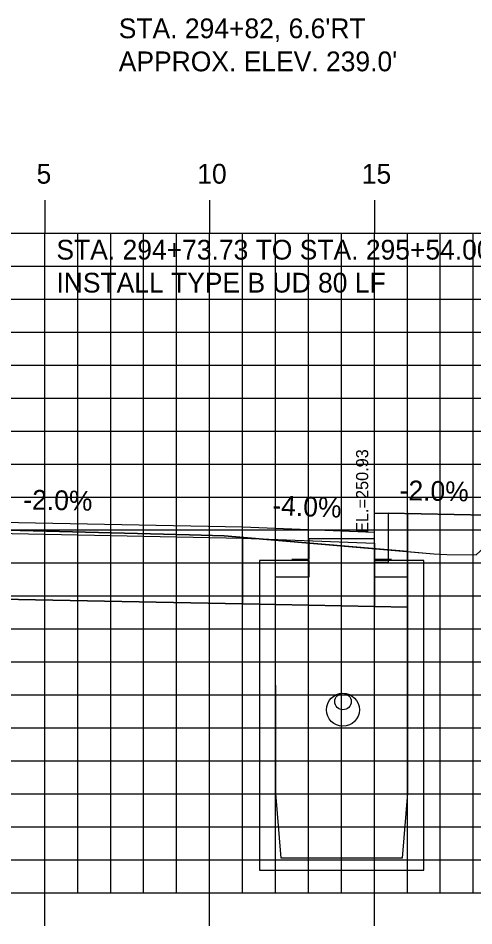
# Model space of a CAD drawing. Extents: x 859352 to 859522, y 366268 to 366378.
# Drawn here: x 859439.32 to 859453.15, y 366306.23 to 366333.75 of the extents above; entities that cross this region are included whole.
import ezdxf

# ---------------------------------------------------------------- set-up
doc = ezdxf.new("R2010")
doc.units = 0
for name, color, linetype in [('ANNOTATION', 7, 'Continuous'), ('D_Curb_Type_1_Rt', 7, 'Continuous'), ('D_Drainage_CB_TypeA1-B1', 7, 'Continuous'), ('D_Drainage_Text', 7, 'Continuous'), ('D_Roadway_Edge_Shoulder', 7, 'Continuous'), ('D_Roadway_FinishedGrade', 7, 'Continuous'), ('D_Roadway_SubGrade', 7, 'Continuous'), ('D_Text_Standard', 7, 'Continuous'), ('H_V ANNOTATION', 7, 'Continuous'), ('JUNK COM EXC', 7, 'Continuous'), ('JUNK FILL', 7, 'Continuous'), ('MAJOR', 7, 'Continuous'), ('MINOR', 7, 'Continuous'), ('PDRAIN', 7, 'Continuous'), ('ROCKS', 7, 'Continuous'), ('S_Roadway_Centerline', 7, 'Continuous')]:
    doc.layers.add(name, color=color, linetype=linetype)

msp = doc.modelspace()

# ---------------------------------------------------------------- linework, layer by layer
at = {"layer": 'D_Curb_Type_1_Rt'}
msp.add_lwpolyline([(859450.546, 366318.75), (859450.546, 366317.25), (859450.129, 366317.25), (859450.129, 366318.75)], close=True, dxfattribs=at)
at = {"layer": 'D_Drainage_CB_TypeA1-B1'}
for p, q in [((859448.153, 366317.311), (859446.644, 366317.311)), ((859446.644, 366317.311), (859446.644, 366315.31)), ((859448.153, 366316.811), (859448.153, 366317.311)), ((859451.63, 366317.311), (859450.121, 366317.311)), ((859450.121, 366317.311), (859450.121, 366316.811)), ((859451.63, 366315.31), (859451.63, 366317.311)), ((859447.136, 366310.255), (859447.129, 366316.811)), ((859447.129, 366316.811), (859448.153, 366316.811)), ((859450.121, 366316.811), (859451.138, 366316.811)), ((859451.138, 366316.811), (859451.138, 366310.255)), ((859446.644, 366315.31), (859446.644, 366307.926)), ((859451.63, 366307.926), (859451.63, 366315.31)), ((859447.3, 366308.286), (859447.136, 366310.255)), ((859451.138, 366310.255), (859450.974, 366308.286)), ((859450.974, 366308.286), (859447.3, 366308.286)), ((859446.644, 366307.926), (859451.63, 366307.926))]:
    msp.add_line(p, q, dxfattribs=at)
msp.add_lwpolyline([(859447.628, 366317.353), (859448.153, 366317.353), (859448.153, 366317.976), (859450.121, 366317.976), (859450.121, 366317.353), (859450.646, 366317.353)], dxfattribs=at)
at = {"layer": 'D_Roadway_Edge_Shoulder'}
msp.add_lwpolyline([(859420.132, 366318.167), (859424.13, 366318.327), (859435.13, 366318.547), (859446.13, 366318.327), (859450.121, 366318.167)], dxfattribs=at)
at = {"layer": 'D_Roadway_FinishedGrade'}
msp.add_lwpolyline([(859450.546, 366318.749), (859453.546, 366318.689)], dxfattribs=at)
at = {"layer": 'D_Roadway_SubGrade'}
msp.add_lwpolyline([(859451.129, 366318.761), (859451.129, 366315.893), (859450.13, 366315.913)], dxfattribs=at)
for points in [[(859424.13, 366315.993), (859424.13, 366317.993), (859435.13, 366318.213), (859446.13, 366317.993), (859446.13, 366315.993), (859435.13, 366316.213)], [(859446.13, 366317.993), (859450.13, 366317.833), (859450.13, 366315.913), (859446.13, 366315.993)]]:
    msp.add_lwpolyline(points, close=True, dxfattribs=at)
at = {"layer": 'JUNK COM EXC'}
msp.add_lwpolyline([(859415.127, 366318.509), (859415.125, 366317.675), (859419.13, 366317.595), (859419.13, 366315.893), (859424.13, 366315.993), (859435.13, 366316.213), (859446.13, 366315.993), (859451.129, 366315.893), (859451.129, 366317.579), (859445.568, 366318.061), (859444.518, 366318.087), (859435.819, 366318.308), (859426.771, 366318.136), (859425.006, 366318.102), (859424.052, 366318.059), (859421.622, 366317.921), (859421.018, 366317.889), (859420.288, 366317.857), (859419.866, 366318.325), (859419.801, 366318.381), (859418.966, 366318.416), (859415.419, 366318.501), (859415.127, 366318.509)], dxfattribs=at)
at = {"layer": 'JUNK FILL'}
msp.add_lwpolyline([(859451.129, 366317.579), (859451.933, 366317.51), (859452.326, 366317.489), (859453.214, 366317.483), (859453.855, 366318.068), (859458.043, 366317.94), (859455.795, 366318.315), (859453.546, 366318.689), (859450.546, 366318.749), (859450.546, 366317.63)], close=True, dxfattribs=at)
at = {"layer": 'MAJOR'}
for p, q in [((859440.129, 366328.238), (859440.129, 366327.236)), ((859445.129, 366328.238), (859445.129, 366327.236)), ((859450.129, 366328.238), (859450.129, 366327.236)), ((859365.129, 366327.236), (859505.129, 366327.236)), ((859365.129, 366327.236), (859505.129, 366327.236)), ((859440.129, 366307.236), (859440.129, 366327.236)), ((859445.129, 366307.236), (859445.129, 366327.236)), ((859450.129, 366307.236), (859450.129, 366327.236)), ((859365.129, 366322.236), (859505.129, 366322.236)), ((859365.129, 366317.236), (859505.129, 366317.236)), ((859365.129, 366312.236), (859505.129, 366312.236)), ((859365.129, 366307.236), (859505.129, 366307.236)), ((859365.129, 366307.236), (859505.129, 366307.236)), ((859440.129, 366306.234), (859440.129, 366307.236)), ((859445.129, 366306.234), (859445.129, 366307.236)), ((859450.129, 366306.234), (859450.129, 366307.236))]:
    msp.add_line(p, q, dxfattribs=at)
at = {"layer": 'MINOR'}
for p, q in [((859441.129, 366307.236), (859441.129, 366327.236)), ((859442.129, 366307.236), (859442.129, 366327.236)), ((859443.129, 366307.236), (859443.129, 366327.236)), ((859444.129, 366307.236), (859444.129, 366327.236)), ((859446.129, 366307.236), (859446.129, 366327.236)), ((859447.129, 366307.236), (859447.129, 366327.236)), ((859448.129, 366307.236), (859448.129, 366327.236)), ((859449.129, 366307.236), (859449.129, 366327.236)), ((859451.129, 366307.236), (859451.129, 366327.236)), ((859452.129, 366307.236), (859452.129, 366327.236)), ((859453.129, 366307.236), (859453.129, 366327.236)), ((859365.129, 366326.236), (859505.129, 366326.236)), ((859365.129, 366325.236), (859505.129, 366325.236)), ((859365.129, 366324.236), (859505.129, 366324.236)), ((859365.129, 366323.236), (859505.129, 366323.236)), ((859365.129, 366321.236), (859505.129, 366321.236)), ((859365.129, 366320.236), (859505.129, 366320.236)), ((859365.129, 366319.236), (859505.129, 366319.236)), ((859365.129, 366318.236), (859505.129, 366318.236)), ((859365.129, 366316.236), (859505.129, 366316.236)), ((859365.129, 366315.236), (859505.129, 366315.236)), ((859365.129, 366314.236), (859505.129, 366314.236)), ((859365.129, 366313.236), (859505.129, 366313.236)), ((859365.129, 366311.236), (859505.129, 366311.236)), ((859365.129, 366310.236), (859505.129, 366310.236)), ((859365.129, 366309.236), (859505.129, 366309.236)), ((859365.129, 366308.236), (859505.129, 366308.236))]:
    msp.add_line(p, q, dxfattribs=at)
at = {"layer": 'PDRAIN'}
for p, q in [((859450.121, 366317.311), (859450.121, 366316.462)), ((859451.138, 366316.811), (859451.138, 366317.073))]:
    msp.add_line(p, q, dxfattribs=at)
for centre, radius in [((859449.176, 366312.786), 0.5), ((859449.176, 366313.036), 0.25)]:
    msp.add_circle(centre, radius, dxfattribs=at)
at = {"layer": 'S_Roadway_Centerline'}
msp.add_lwpolyline([(859412.42, 366318.362), (859414.836, 366318.508), (859414.896, 366318.514), (859415.419, 366318.501), (859418.966, 366318.416), (859419.801, 366318.381), (859419.866, 366318.325), (859420.288, 366317.857), (859421.018, 366317.889), (859421.622, 366317.921), (859424.052, 366318.059), (859425.006, 366318.102), (859426.771, 366318.136), (859435.819, 366318.308), (859444.518, 366318.087), (859445.568, 366318.061), (859451.933, 366317.51), (859452.326, 366317.489), (859453.214, 366317.483), (859453.855, 366318.068), (859453.912, 366318.103), (859458.18, 366317.935), (859464.006, 366317.706), (859478.018, 366317.015)], dxfattribs=at)

# ---------------------------------------------------------------- texts
at = {"layer": 'ANNOTATION'}
for s, rotation, p in [('-2.0%', 358.8541, (859450.889, 366319.143)), ('-2.0%', 358.8542, (859439.473, 366318.86)), ('-4.0%', 357.7094, (859447.025, 366318.691))]:
    msp.add_text(s, height=0.6, rotation=rotation, dxfattribs=at).set_placement(p)
at = {"layer": 'D_Drainage_Text'}
for s, p in [('STA. 294+73.73 TO STA. 295+54.00 RT', (859440.482, 366326.434)), ('INSTALL TYPE B UD 80 LF', (859440.482, 366325.434))]:
    msp.add_text(s, height=0.6, dxfattribs=at).set_placement(p)
at = {"layer": 'D_Text_Standard'}
msp.add_text(' EL.=250.93', height=0.36848, rotation=90, dxfattribs=at).set_placement((859449.941, 366318.012))
at = {"layer": 'H_V ANNOTATION'}
for s, p in [('5', (859439.88, 366328.736)), ('10', (859444.755, 366328.736)), ('15', (859449.747, 366328.736))]:
    msp.add_text(s, height=0.6, dxfattribs=at).set_placement(p)
at = {"layer": 'ROCKS'}
for s, p in [("STA. 294+82, 6.6'RT", (859442.373, 366333.145)), ("APPROX. ELEV. 239.0'", (859442.373, 366332.143))]:
    msp.add_text(s, height=0.6, dxfattribs=at).set_placement(p)

doc.saveas('drawing.dxf')
